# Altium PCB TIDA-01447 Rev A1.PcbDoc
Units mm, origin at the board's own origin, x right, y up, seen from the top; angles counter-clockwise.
Board outline 16 x 21 mm, 2 copper layers (Top Layer, Bottom Layer), stack 1.575 mm thick; 26 components, 8 nets, 40 pads, 0 vias.
Unrouted connection lines stored in the file: 1.
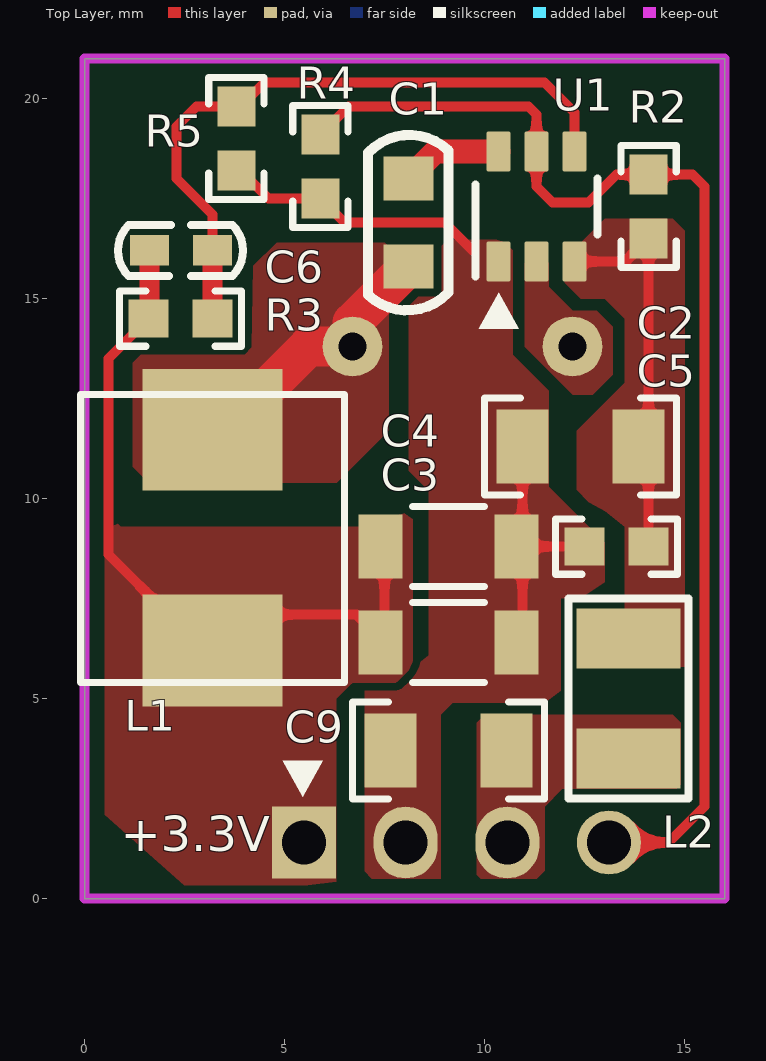
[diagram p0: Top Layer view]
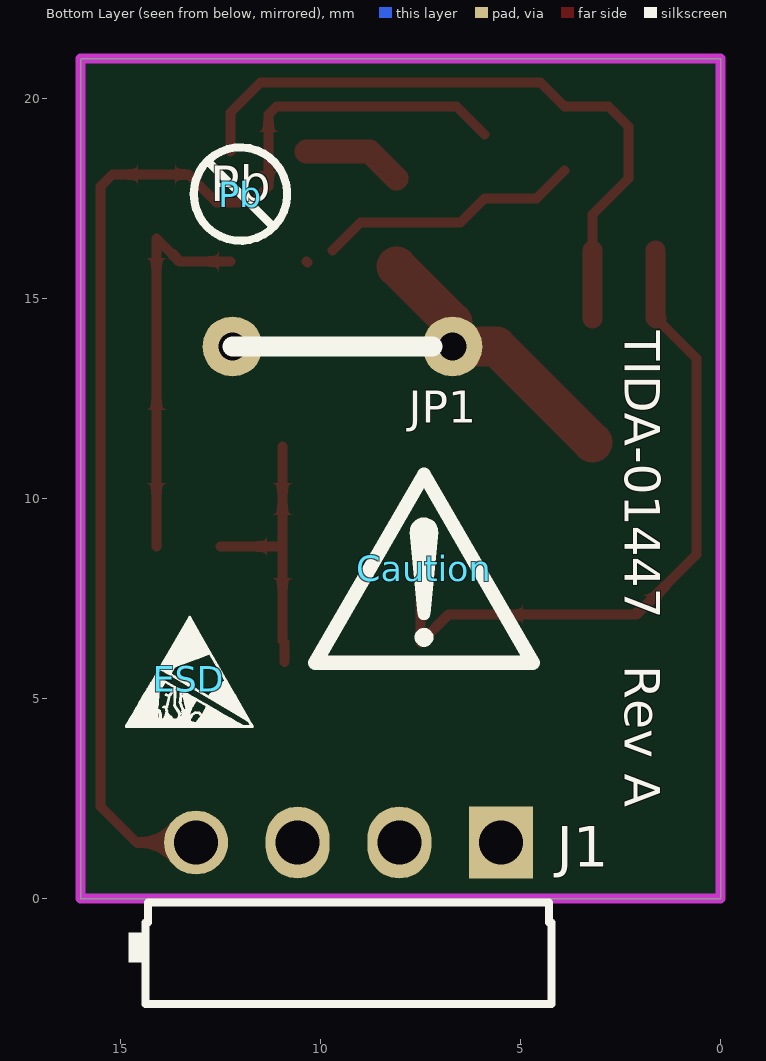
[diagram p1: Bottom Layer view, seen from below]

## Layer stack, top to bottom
Top Solder: solder mask 0.0102, Solder Resist, Dk 3.5
Top Layer: signal copper 0.0356
Dielectric1: core 1.5037, FR-4, Dk 4.8
Bottom Layer: signal copper 0.0356
Bottom Solder: solder mask 0.0102, Solder Resist, Dk 3.5

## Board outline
0,0 0,21 16,21 16,0

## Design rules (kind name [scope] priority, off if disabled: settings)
AcuteAngle [All] p1: minimum=4.50000000000000E+0001 checktracksonly=FALSE
AssemblyTestPointUsage [All] p1: valid=2
Clearance Clearance_Keepouts [((IsTrack Or IsArc) And Not InPoly) And IsFree and IsKeepOut vs ((IsTrack Or IsArc) And Not InPoly) And IsFree and IsKeepOut] p1 off: gap=0
Clearance Clearance_BoardEdge_MountingHoles [OnCopper and InComponentClass('Mounting Holes') vs IsKeepOut] p2 off: gap=1.016
Clearance Clearance_BoardEdge_Poly [OnCopper and InPoly vs IsKeepOut] p3 off: gap=0.635
Clearance Clearance_BoardEdge [OnCopper and Not InComponentClass('Logo') and not InComponentClass('FiducialMark') and not InRegion(1000,500,4000,800) and Not IsKeepout vs IsKeepOut] p4 off: gap=1.905
Clearance Clearance_Poly [InPolygon] p5 off: gap=0.635
Clearance [All] p6: gap=0.2
ComponentClearance ComponentClearance_MountingHoles_FiducialMarks [InComponentClass('Mounting Holes') vs InComponentClass('FiducialMark')] p1: gap=1.27 collisioncheckmode=3 verticalgap=0.254 showdistances=FALSE
ComponentClearance ComponentClearance_Shunt [InComponentClass('Header') vs InComponentClass('Shunt')] p2: gap=0 collisioncheckmode=3 verticalgap=0 showdistances=FALSE
ComponentClearance ComponentClearance_Logo [InComponentClass('Logo')] p3: gap=1.27 collisioncheckmode=3 verticalgap=0.254 showdistances=FALSE
ComponentClearance ComponentClearance_ScrewToNut [(HasFootprint('NY PMS 440 0025 PH')) vs (HasFootprint('Keystone_1902C'))] p4: gap=0.127 collisioncheckmode=3 verticalgap=0.254 showdistances=FALSE
ComponentClearance ComponentClearance_MountingHoles [InComponentClass('Mounting Holes')] p5: gap=6.35 collisioncheckmode=3 verticalgap=2540 showdistances=FALSE
ComponentClearance ComponentClearance_SmallPassives [HasFootprint('0201*') or HasFootprint('0402*') or HasFootprint('0508') or HasFootprint('0603*') or HasFootprint('0612') or HasFootprint('0805*') or HasFootprint('0815*') or HasFootprint('0830*') or HasFootprint('1206*') or HasFootprint('1210*') or HasFootprint('1808*') or HasFootprint('1812*') or HasFootprint('1825*') or HasFootprint('2010*') or HasFootprint('2220*') or HasFootprint('2225*') or HasFootprint('2512*') or HasFootprint('2728*') or HasFootprint('3518*') vs HasFootprint('0201*') or HasFootprint('0402*') or HasFootprint('0508') or HasFootprint('0603*') or HasFootprint('0612') or HasFootprint('0805*') or HasFootprint('0815*') or HasFootprint('0830*') or HasFootprint('1206*') or HasFootprint('1210*') or HasFootprint('1808*') or HasFootprint('1812*') or HasFootprint('1825*') or HasFootprint('2010*') or HasFootprint('2220*') or HasFootprint('2225*') or HasFootprint('2512*') or HasFootprint('2728*') or HasFootprint('3518*')] p6: gap=0.508 collisioncheckmode=3 verticalgap=0.254 showdistances=FALSE
ComponentClearance ComponentClearance_THtoSMT [IsThruComponent vs IsSMTComponent] p7: gap=2.54 collisioncheckmode=3 verticalgap=0.762 showdistances=FALSE
ComponentClearance ComponentClearance_THtoTH [IsThruComponent vs IsThruComponent] p8: gap=3 collisioncheckmode=3 verticalgap=0.762 showdistances=FALSE
ComponentClearance [All] p9: gap=1.016 collisioncheckmode=3 verticalgap=0.254 showdistances=FALSE
DiffPairsRouting [All] p1: maxlimit=2.54 minlimit=0.254 mostfreqgap=0.254 toplayer_minwidth=0.381 toplayer_maxwidth=0.381 toplayer_prefwidth=0.381 bottomlayer_minwidth=0.381 bottomlayer_maxwidth=0.381 bottomlayer_prefwidth=0.381 maxuncoupledlength=25.4
FabricationTestPointUsage TestPointUsage [All] p1: valid=2 allowmultiple=FALSE
FabricationTestpoint Testpoint [All] p1: side=3 testpointundercomponent=TRUE minsize=1.016 maxsize=2.54 preferedsize=1.524 minholesize=0 maxholesize=1.016 preferedholesize=0.813 testpointgrid=0.025 allowsidetop=TRUE allowsidebottom=TRUE usegrid=TRUE gridtolerance=0
FanoutControl Fanout_LCC [IsLCC] p1: bgadir=Out bgaviamode=Centered fanoutstyle=Auto fanoutdirection=Alternating viagrid=0.025 // Fanout_LCC (Default Rule)
FanoutControl Fanout_BGA [IsBGA] p2: bgadir=Out bgaviamode=Centered fanoutstyle=Auto fanoutdirection=Alternating viagrid=0.025 // Fanout_BGA (Default Rule)
FanoutControl Fanout_Default [All] p4: bgadir=Out bgaviamode=Centered fanoutstyle=Auto fanoutdirection=Alternating viagrid=0.025 // Fanout_Default (Default Rule)
FanoutControl Fanout_Small [(CompPinCount < 5)] p5: bgadir=Out bgaviamode=Centered fanoutstyle=Auto fanoutdirection=OutThenIn viagrid=0.025 // Fanout_Small (Default Rule)
HoleSize [All] p1: absolutevalues=TRUE maxlimit=6.375 minlimit=0.203 maxpercent=80.000 minpercent=20.000
MinimumAnnularRing MinimumAnnularRing_ThermalPadVias [IsVia and InAnyComponent] p1: minimumring=0.15
MinimumAnnularRing [All] p2: minimumring=0.229
MinimumSolderMaskSliver MinimumSolderMaskSliver_Logo [InComponentClass('Logo') vs InComponentClass('Logo')] p1: minsoldermaskwidth=0.018
MinimumSolderMaskSliver [All] p2: minsoldermaskwidth=0.1
PlaneConnect [All] p1: planeconnectstyle=Relief reliefexpansion=0.254 reliefentries=4 reliefconductorwidth=0.254 reliefairgap=0.254
PolygonConnect [All] p1: connectstyle=Direct reliefconductorwidth=0.254 reliefentries=4 polygonreliefangle="90 Angle" airgapwidth=0.254
RoutingVias ThermalPadVias [IsVia and InAnyComponent] p1: holewidth=0.2 width=0.5 viastyle="Through Hole" minholewidth=0.2 minwidth=0.5 maxholewidth=0.33 maxwidth=0.6
RoutingVias [All] p2: holewidth=0.406 width=0.864 viastyle="Through Hole" minholewidth=0.2 minwidth=0.66 maxholewidth=1.016 maxwidth=1.651
SilkToBoardRegionClearance [Not ((IsComment or IsDesignator) And (Hide <> 'False')) and not InRegion(1000,500,4000,800)] p1:
SilkToSilkClearance SilkToSilkClearance_Pb-FreeLogo [(HasFootprint('Pb-Free_Overlay_Medium') OR HasFootprint('Pb-Free_Overlay_Small')) vs (HasFootprint('Pb-Free_Overlay_Medium') OR HasFootprint('Pb-Free_Overlay_Small'))] p1: silktosilkclearance=0
SilkToSilkClearance [All] p2: silktosilkclearance=0.102
SilkToSolderMaskClearance SilkToComonentPadClearance [IsPad and InAnycomponent] p1: minsilkscreentomaskgap=0.127 clearancetoexposedcopper=TRUE
SilkToSolderMaskClearance "Silk to Solder Mask Opening" [All] p2: minsilkscreentomaskgap=0.102 clearancetoexposedcopper=FALSE
SolderMaskExpansion [All] p1: expansion=0.05
UnpouredPolygon [All] p1: allowunpoured=FALSE
Width [All] p1: maxlimit=2.54 minlimit=0.152 preferedwidth=0.254 checkconnectedcopper=TRUE
14 further rules are at their usual default settings.

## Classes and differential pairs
component class TIDA-01447: C1 C2 C3 C4 C5 C6 C9 J1 JP1 L1 L2 R2 R3 R4 R5 U1

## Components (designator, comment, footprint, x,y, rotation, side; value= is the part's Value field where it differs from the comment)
C1 "GRM21BR71E104KA01L" C/0805/SMT1 8.1,15.9 r90 top
C2 "GRM31CR71E106KA12L" 1206 12.4,11.3 r180 top
C3 "GCM31CR71A226KE02" 1206_190 9.1,6.4 r0 top
C4 "GCM31CR71A226KE02" 1206_190 9.1,8.8 r0 top
C5 "GRM188R71E104KA01D" 0603 13.3,8.8 r180 top
C6 "06033C101KAT2A" C/0603 2.4,16.2 r0 top
C9 "GRM31CR71E106KA12L" 1206 9.1,3.7 r180 top
Caution "CAUTION.  READ USER GUIDE BEFORE USE" IEC_Caution_small 7.412,8.254 r180 bottom
ESD "ESD Susceptible" ESD_Overlay_small 13.3,5.5 r180 bottom
H5 "1902C" Keystone_1902C -38.24,60.15 r180 bottom locked
H6 "1902C" Keystone_1902C 77.33,60.15 r180 bottom locked
H7 "1902C" Keystone_1902C -38.24,-17.32 r180 bottom locked
H8 "1902C" Keystone_1902C 77.33,-17.32 r180 bottom locked
J1 "61300411021" Wurth_61300411021 9.3,1.4 r180 bottom
JP1 "CRCW0603100KFKEA" JUMP-5 7.2,13.8 r0 bottom
L1 "ABG06B45M220" WE-PD-M 3.2,9 r270 top
L2 "ABG03A15M4R7" Inductor-EPL3015 13.6,5 r90 top
Pb "Pb-Free Symbol" Pb-Free_Overlay_Small 12.001,17.611 r180 bottom
R2 "CRCW0603510KJNEA" 0603 14.1,17.3 r270 top
R3 "CRCW0603100KFKEA" 0603 2.4,14.5 r180 top
R4 "CRCW0603118KFKEA" 0603 5.9,18.3 r90 top
R5 "CRCW060313K3FKEA" 0603 3.8,19 r90 top
U1 "TPS54202DDCR" DDC0006A_N 11.3,17.3 r90 top
ZZ2 "These assemblies are ESD sensitive, ESD precautions shall be observed." AssemblyNote -38.621,74.859 r0 top
ZZ3 "These assemblies must be clean and free from flux and all contaminants. Use of no clean flux is not acceptable." AssemblyNote -38.621,72.61 r0 top
ZZ4 "These assemblies must comply with workmanship standards IPC-A-610 Class 2, unless otherwise specified." AssemblyNote -38.621,70.361 r0 top

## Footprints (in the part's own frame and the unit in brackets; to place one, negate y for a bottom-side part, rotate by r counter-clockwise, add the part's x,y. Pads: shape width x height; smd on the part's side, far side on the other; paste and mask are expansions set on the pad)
0603 [mm] "0603 from SM-752 data"
  rect 1x0.95 smd: 1(-0.8,0) 2(0.8,0)
  silkscreen extent -1.52,-0.69 1.52,0.69, body extent -0.87,-0.47 0.87,0.47, height 1
1206 [mm] "1206 from SM-752 data"
  rect 1.3x1.85 smd: 1(-1.45,0) 2(1.45,0)
  silkscreen extent -2.4,-1.21 2.4,1.21, body extent -1.7,-0.9 1.7,0.9, height 1.35
1206_190 [mm] "1206_190"
  rect 1.1x1.6 smd: 1(-1.7,0) 2(1.7,0)
  silkscreen extent -0.9,-1 0.9,1, body extent -1.75,-0.95 1.75,0.95, height 1.9
AssemblyNote [mm] "Assembly Note"
C/0603 [mil]
  rect 38x30 smd: 1(-30.52,0.06) 2(31.48,0.06)
  silkscreen extent -62,-25 62,25
C/0805/SMT1 [mm]
  rect 1.1x1.25 smd: 1(-0.1,0) 2(2.1,0)
  silkscreen extent -1.19,-1 3.19,1.01
DDC0006A_N [mm]
  rrect17% 1x0.6 smd: 1(-1.375,0.95) 2(-1.375,0) 3(-1.375,-0.95) 4(1.375,-0.95) 5(1.375,0) 6(1.375,0.95)
  silkscreen extent -1.75,-1.52 0.7,1.53, body extent -1.43,-1.48 1.43,1.49, height 0.92
ESD_Overlay_small [mm]
  silkscreen extent -1.58,-1.23 1.62,1.55
IEC_Caution_small [mm]
  silkscreen extent -2.72,-2.36 2.72,2.35
Inductor-EPL3015 [mm]
  rect 1.5x2.6 smd: 1(-1.5,0) 2(1.5,0)
  silkscreen extent -2.5,-1.5 2.5,1.5
JUMP-5 [mm]
  round 1.5 hole 0.7: 1(-0.5,0) 2(5,0)
  silkscreen extent 0,0 5,0
Keystone_1902C [mm] "Hex Standoff, 4-40 threaded, nylon"
  body extent -3.68,-3.2 3.71,3.2, height 12.73
Pb-Free_Overlay_Small [mm]
  silkscreen extent -1.17,-1.17 1.16,1.17
WE-PD-M [mm] "Wurth Elektronik recommended land pattern, 2008-01-04"
  rect 2.4x3.5 smd: 1(-3.035,0) 2(3.004,0)
  silkscreen extent -3.6,-3.3 3.6,3.3, body extent -3.81,-3.84 3.81,3.79, height 4.5
Wurth_61300411021 [mm] "Header, 2.54 mm, 4x1, R/A, TH"
  round 1.6 hole 1.1: 1(-3.81,0)
  oval 1.6x1.8 hole 1.1: 2(-1.27,0) 3(1.27,0)
  rect 1.6x1.8 hole 1.1: 4(3.81,0)
  silkscreen extent -5.5,-4.04 5.08,-1.5, body extent -5.08,-10.04 5.08,0.32, height 2.55

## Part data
C1: "CAP, CERM, 0.1 μF, 25 V, +/- 10%, X7R, 0805"
C2 C9: "CAP, CERM, 10 μF, 25 V, +/- 10%, X7R, 1206"
C3 C4: "CAP, CERM, 22 μF, 10 V, +/- 10%, X7R, AEC-Q200 Grade 1, 1206_190"
C5: "CAP, CERM, 0.1 μF, 25 V, +/- 10%, X7R, 0603"
C6: "CAP, CERM, 100 pF, 25 V, +/- 10%, X7R, 0603"
Caution: library part IEC_Caution, "IEC 61010-1 Caution Warning"
ESD: library part ESD_Susceptible, "ESD Susceptible Symbol"
H5 H6 H7 H8: "Standoff, Hex, 0.5\"L #4-40 Nylon"
J1: "Header, 2.54 mm, 4x1, Gold, R/A, TH"
JP1 R3: "RES, 100 k, 1%, 0.1 W, 0603"
L1 L2: library part LPS8045B-333MRB, "Inductor, Shielded, Ferrite, 22 μH, 3.3 A, SMD"
Pb: library part Pb-Free
R2: "RES, 510 k, 5%, 0.1 W, 0603"
R4: "RES, 118 k, 1%, 0.1 W, 0603"
R5: "RES, 13.3 k, 1%, 0.1 W, 0603"
U1: "4.5-V TO 28-V INPUT, 2-A OUTPUT, EMI FRIENDLY SYNCHRONUOUS STEP-DOWN CONVERTOR, DDC0006A"
ZZ2 ZZ3 ZZ4: library part AssemblyNote

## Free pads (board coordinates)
  rect 3.5x2 smd: 0(3.2,6.6)
  rect 3.5x2.4 smd: 0(3.2,11.4)

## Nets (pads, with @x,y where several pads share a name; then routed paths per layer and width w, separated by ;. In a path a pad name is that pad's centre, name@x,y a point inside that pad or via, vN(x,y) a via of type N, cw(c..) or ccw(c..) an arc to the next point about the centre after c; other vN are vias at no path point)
+5V: C3.1 C4.1 C6.1 J1.4 L1.2 pad.0@3.2,6.6 R3.2 | length 18
  Top Layer w0.254: R3.2 0.6,13.5 0.6,8.6 2.104,7.097 6.804,7.097 7.5,6.4 C4.1@7.5,8.6
  Top Layer w0.5: R3.2 1.625,14.525 C6.1
EN: J1.1 R2.1 R4.2 U1.5 | length 30.6
  Top Layer w0.254: R4.2 6.6,19.8 11.1,19.8 11.3,19.6 U1.5 11.3,17.8 11.7,17.4 12.6,17.4 13.3,18.1 R2.1 15.2,18.1 15.5,17.8 15.5,2.3 14.6,1.4 J1.1
GND: C2.2 C3.2 C4.2 C5.2 C9.2 J1.3 R4.1 R5.1 U1.1 | length 13.6
  Top Layer w0.254: R5.1@3.9,18.2 4.6,17.5 R4.1 6.5,16.9 9,16.9 9.7,16.2 ; U1.1@10.325,15.9 U1.1 ; C3.2@10.9,5.912 C3.2@10.9,6.4 ; C3.2@10.95,6.45 C4.2@10.95,8.8 ; C2.2 C4.2@10.95,8.8 ; C5.2 C4.2@10.95,8.8
NetC1_1: C1.1 JP1.1 JP1.2 L1.1 pad.0@3.2,11.4 U1.2 | length 7.1
  Top Layer w1: L1.1@3.2,11.4 5.6,13.8 JP1.1 6.7,14.4 C1.1
NetC1_2: C1.2 U1.6 | length 2.5
  Top Layer w0.6: C1.2 8.775,18.675 U1.6
NetC2_1: C2.1 C5.1 L2.2 R2.2 U1.3 | length 9.8
  Top Layer w0.254: U1.3 13.525,15.925 R2.2 C5.1
NetC6_2: C6.2 R3.1 R5.2 U1.4 | length 16.9
  Top Layer w0.254: C6.2 3.2,17.1 2.3,18 2.3,19.3 2.8,19.8 R5.2 3.9,19.8 4.5,20.4 11.5,20.4 12.25,19.65 U1.4
  Top Layer w0.5: R3.1 C6.2
VIN: C9.1 J1.2 L2.1

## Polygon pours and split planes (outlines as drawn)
VIN on Top Layer "Top Layer-No Net 5" (solid, remove dead copper, pour order 7): 10.7,4.6 14.7,4.6 14.9,4.4 14.9,3 14.9,2.851 14.795,2.746 11.946,2.746 11.5,2.3 11.5,0.7 11.3,0.5 9.9,0.5 9.8,0.6 9.8,4.4 10,4.6
GND on Top Layer "Top Layer-No Net" (solid, remove dead copper, pour order 2): 10.535,16.397 10.7,16.232 10.7,13.8 10.7,13.6 11.2,13.1 11.6,12.7 11.6,11.8 11.6,10.3 12.1,9.8 13,8.9 13,7.908 12.523,7.577 11.9,7.5 11.9,6.087 11.9,5.2 11.5,4.9 9.2,4.9 8.9,4.6 8.9,0.5 7,0.5 7,5.6 8.033,5.6 8.6,6.087 8.6,10.2 8.3,10.5 8.1,10.7 8.1,14.2 8.1,15.5 9.072,16.472 10.535,16.472
NetC2_1 on Top Layer "Top Layer-No Net 1" (solid, remove dead copper, pour order 4): 12,16.1 12,15.4 12.3,15.1 12.4,15 12.9,15 13,15 13.4,14.6 13.5,14.5 13.5,13.4 13.5,12.9 13.2,12.6 12.3,11.7 12.3,11 12.3,10.223 12.611,9.912 13.015,9.679 13.5,9.3 13.5,8.8 13.5,5.8 15,5.8 15,9.3 15,16.7 14.8,16.9 14.7,17 13.6,17 13,17 12.4,16.4
NetC1_1 on Top Layer "Top Layer-No Net 2" (solid, remove dead copper, pour order 6): 7.6,14.008 7.6,11.7 7,11.1 6.3,10.4 2.5,10.4 1.6,10.4 1.2,10.8 1.2,13.4 1.4,13.6 3.8,13.6 4,13.6 4.181,13.781 4.219,15.819 4.8,16.4 7.5,16.4 7.6,16.3
NetC1_1 on Top Layer "Top Layer-No Net 3" (solid, remove dead copper, pour order 8): 11.6,15.9 11.6,15.3 11.8,15.1 12.2,14.7 12.6,14.7 12.8,14.7 13,14.5 13.2,14.3 13.2,13.7 13.2,13.1 12.9,12.8 12.7,12.6 12.3,12.6 12.2,12.6 11.7,13.1 11,13.8 11,15 11,15.9
+5V on Top Layer "Top Layer-No Net 4" (solid, remove dead copper, pour order 10): 8.2,9.7 8.2,5.8 7.8,5.4 6.7,5.4 6.632,5.332 6.3,5 6.3,0.42 2.857,0.008 0.5,2.1 0.5,8.8 0.6,8.9 0.6,9.6 0.9,9.3 6.9,9.3

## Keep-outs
Keep-Out Layer:
  lines w0.254: -43.447,-22.4 ccw(c-43.32,-22.4) -43.32,-22.527 cw(c-43.32,-22.4) -43.447,-22.4 ; 0,0 0,21 16,21 16,0 0,0

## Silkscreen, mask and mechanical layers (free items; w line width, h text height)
Top Overlay:
  region: 10.35,15.15 9.85,14.25 10.85,14.25
  region: 5.45,2.55 5.95,3.45 4.95,3.45
  text "+3.3V" at 0.9,0.9 h1.5
Bottom Overlay:
  text "TIDA-01447   Rev A" at 2.7,14.2 h1.52 r90
Top Paste:
  text ".Layer_Name" at -28.664,-44.206 h1.52
Bottom Paste:
  text ".Layer_Name" at -28.664,-44.206 h1.52
Top Solder:
  lines w1: 8.6,13.1 8.6,14.5 ; 9.1,10.6 9.1,12 ; 10.1,13.2 10.1,14.8 ; 14.2,13.3 14.2,15
Bottom Solder:
  text ".Layer_Name" at -28.664,-44.206 h1.52
Drill Guide:
  text ".Layer_Name" at -28.664,-44.206 h1.52
M1 Board Outline:
  lines w0.254: -43.32,-22.4 82.41,-22.4 82.41,65.23 -43.32,65.23 -43.32,-22.4
  text ".Layer_Name" at -28.664,-44.206 h1.52
M2 Board Dimensions:
  rectangle: -40.145,-32.56 -30.62,-29.385
  rectangle: -43.32,-29.385 -40.145,-26.21
  lines w0.178: -43.32,-29.385 -17.92,-29.385 ; -40.145,-32.56 -40.145,-26.21 ; -36.97,-32.56 -36.97,-26.21 ; -30.62,-32.56 -30.62,-26.21 ; -24.27,-32.56 -24.27,-26.21 ; -43.32,-32.56 -43.32,-26.21 -17.92,-26.21 -17.92,-32.56 -43.32,-32.56
  text ".Layer_Name" at -28.664,-44.206 h1.52
M3 3D STEP Top:
  text ".Layer_Name" at -28.664,-44.206 h1.52
M4 3D STEP Bottom:
  text ".Layer_Name" at -28.664,-44.206 h1.52
M5 Assembly Top:
  lines w0.254: -50.737,-46.026 116.903,-46.026 ; -50.737,-40.862 116.954,-40.862 ; -50.737,-35.697 -50.737,-51.191 50.99,-51.191 116.954,-51.191 116.954,-35.697 -50.724,-35.697 -50.724,-51.191 -10.706,-51.191 ; 11.874,-51.191 11.874,-35.697 ; 44.056,-40.862 44.056,-35.697 ; 65.392,-40.862 65.392,-35.697 ; 81.191,-51.356 81.191,-46.204
  text "COMPONENTS MARKED 'DNP' SHOULD NOT BE POPULATED." at -14.021,-30.49 h1.52
  text "ASSEMBLY VARIANT:" at -14.034,-33.424 h1.52
  text ".VariantName" at 12.281,-33.424 h1.52
  text "PCB VIEWED FROM TOP SIDE" at -49.124,-39.054 h1.52
  text "BOARD #:" at 13.779,-39.054 h1.52
  text ".PRJ_Number" at 27.635,-39.054 h1.52
  text "REV:" at 49.085,-39.054 h1.52
  text ".PCB_Rev" at 56.489,-39.054 h1.52
  text "SVN REV:" at 70.37,-39.054 h1.52
  text ".VersionControl_RevNumber" at 83.223,-39.054 h1.52
  text "TID #:" at 13.779,-44.219 h1.52
  text ".TID" at 27.635,-44.219 h1.52
  text "PLOT NAME =" at -49.124,-49.434 h1.52
  text ".plot_File_Name" at -28.664,-49.434 h1.52
  text "GENERATED    :" at 13.83,-49.434 h1.52
  text ".Print_Date" at 35.915,-49.434 h1.52
  text ".Print_Time" at 54.432,-49.434 h1.52
  text "TEXAS INSTRUMENTS" at 86.55,-49.434 h1.52
M6 Assembly Bottom:
  lines w0.254: -50.749,-40.874 116.941,-40.874 ; -50.699,-46.039 116.941,-46.039 ; -14.986,-51.369 -14.986,-46.217 ; 0.813,-40.874 0.813,-35.71 ; 22.149,-40.874 22.149,-35.71 ; 54.33,-51.204 54.33,-35.71 ; 76.911,-51.204 116.929,-51.204 116.929,-35.71 -50.749,-35.71 -50.749,-51.204 15.214,-51.204 116.941,-51.204 116.941,-35.71
  text "COMPONENTS MARKED 'DNP' SHOULD NOT BE POPULATED." at 111.671,-30.477 h1.52
  text ".VariantName" at 85.153,-33.424 h1.52
  text "ASSEMBLY VARIANT:" at 111.544,-33.424 h1.52
  text ".VersionControl_RevNumber" at -17.018,-39.067 h1.52
  text "SVN REV:" at -4.166,-39.067 h1.52
  text ".PCB_Rev" at 9.715,-39.067 h1.52
  text "REV:" at 17.119,-39.067 h1.52
  text ".PRJ_Number" at 38.57,-39.067 h1.52
  text "BOARD #:" at 52.425,-39.067 h1.52
  text "PCB VIEWED FROM BOTTOM SIDE" at 115.328,-39.067 h1.52
  text ".TID" at 38.57,-44.231 h1.52
  text "TID #:" at 52.425,-44.231 h1.52
  text "TEXAS INSTRUMENTS" at -20.346,-49.447 h1.52
  text ".Print_Time" at 11.773,-49.447 h1.52
  text ".Print_Date" at 30.289,-49.447 h1.52
  text "GENERATED    :" at 52.375,-49.447 h1.52
  text ".plot_File_Name" at 94.869,-49.447 h1.52
  text "PLOT NAME =" at 115.328,-49.447 h1.52
M9 Title Sheet:
  drawing of 57 lines, arcs and shapes, not listed
  text "1" at -24.528,181.727 h1.78
  text "2" at 38.862,181.727 h1.78
  text "3" at 102.091,181.727 h1.78
  text "4" at 165.76,181.727 h1.78
  text "5" at 229.235,181.727 h1.78
  text "6" at 292.862,181.727 h1.78
  text "A" at -53.899,152.695 h1.78
  text "A" at 322.021,152.695 h1.78
  text "B" at -53.899,92.243 h1.78
  text "B" at 322.021,92.243 h1.78
  text "C" at -53.899,31.918 h1.78
  text "C" at 322.021,31.918 h1.78
  text "PROJECT TITLE:" at 244.805,-15.351 h1.14
  text "TIDA-00948" at 246.075,-18.738 h1.78
  text "DESIGNED FOR:" at 244.805,-22.997 h1.14
  text "D" at -53.899,-28.28 h1.78
  text "D" at 322.021,-28.28 h1.78
  text "FILE NAME:" at 244.805,-30.617 h1.14
  text ".PCB_File_Name_No_Path" at 246.075,-33.665 h1.78
  text "Texas Instruments (TI) and/or its licensors do not warrant the accuracy or completeness of this specification" at 118.58,-37.776 h1.14
  text "ENGINEER:" at 244.805,-37.983 h1.14
  text "LAYOUT BY:" at 283.032,-37.983 h1.14
  text "or any information contained therein. TI and/or its licensors do not warrant that this design will meet" at 117.437,-40.637 h1.14
  text "Jason Tao" at 246.075,-41.92 h1.78
  text "Jason Tao" at 284.315,-41.92 h1.78
  text "the specifications, will be suitable for your application or fit for any particular purpose, or will operate in" at 117.437,-43.499 h1.14
  text ".Layer_Name" at -28.664,-44.206 h1.52
  text "ALTIUM DESIGNER VERSION:" at 283.032,-45.857 h1.14
  text "an implementation. TI and/or its licensors do not warrant that the design is production worthy. You should" at 117.437,-46.361 h1.14
  text "completely validate and test your design implementation to confirm the system functionality for your application." at 118.58,-49.222 h1.14
  text ".print_Scale" at 246.075,-49.243 h1.78
  text ".Application_BuildNumber" at 284.315,-49.243 h1.78
  text "1" at -24.528,-54.493 h1.78
  text "2" at 38.862,-54.493 h1.78
  text "3" at 102.091,-54.493 h1.78
  text "4" at 165.76,-54.493 h1.78
  text "5" at 229.235,-54.493 h1.78
  text "6" at 292.862,-54.493 h1.78
M10 Fab Notes:
  drawing of 173 lines, arcs and shapes, not listed
  text "DESIGN INFORMATION" at 271.056,135.105 h1.52
  text "MIN. TRACK WIDTH:" at 254.684,130.533 h1.52
  text "8" at 282.529,130.533 h1.52
  text "MIL" at 286.46,130.533 h1.52
  text "MIN. CLEARANCE:" at 254.684,127.181 h1.52
  text "0.2" at 281.005,127.181 h1.52
  text "mm" at 286.46,127.181 h1.52
  text "MIN. VIA PAD SIZE:" at 254.684,123.828 h1.52
  text "24" at 281.767,123.828 h1.52
  text "MIL" at 286.46,123.828 h1.52
  text "0.05mm (2MIL)" at 272.337,120.228 h1.52
  text "MINIMUM ANNULAR RING" at 246.322,120.12 h1.52
  text "EXTERNAL" at 290.321,120.12 h1.52
  text "PER" at 251.402,117.122 h1.52
  text "IPC-D-275 CLASS 2 LEVEL C" at 256.99,117.122 h1.52
  text "MIL, HOLES" at 294.791,114.27 h1.52
  text "+/-" at 284.823,114.252 h1.52
  text "+/-" at 306.514,114.252 h1.52
  text "REGISTRATION TOLERANCES:" at 246.322,114.125 h1.52
  text "METAL" at 276.796,114.125 h1.52
  text "5" at 291.432,114.125 h1.52
  text "3" at 312.59,114.125 h1.52
  text "MIL" at 315.543,114.125 h1.52
  text "+/-" at 306.514,111.255 h1.52
  text "HOLE SIZE TOLERANCE (UNLESS OTHERWISE SPECIFIED):" at 246.322,111.128 h1.52
  text "3" at 312.59,111.128 h1.52
  text "MIL" at 315.543,111.128 h1.52
  text "MATERIAL:" at 244.423,105.808 h1.52
  text "FR-4 High Tg" at 269.479,102.243 h1.52
  text "FR-408" at 255.116,102.025 h1.52
  text "OTHER" at 292.911,102.025 h1.52
  text "X" at 265.544,101.933 h1.52
  text "62 MIL (1.6mm) +/-10%" at 263.247,97.892 h1.52
  text "THICKNESS:" at 246.322,97.784 h1.52
  text "X" at 259.991,97.784 h1.52
  text "OTHER" at 295.883,97.784 h1.52
  text "TOLERANCE:" at 246.322,93.77 h1.52
  text "X" at 267.64,93.77 h1.52
  text "ANSI IPC-6012 TYPE 3 CLASS 2" at 272.389,93.77 h1.52
  text "OTHER +/-" at 272.388,89.808 h1.52
  text "BOW & TWIST:" at 246.322,85.82 h1.52
  text "X" at 267.64,85.82 h1.52
  text "ANSI IPC-6012 TYPE 3 CLASS 2" at 272.389,85.82 h1.52
  text "OTHER +/-" at 272.388,81.794 h1.52
  text "DRILLING:" at 244.423,78.276 h1.52
  text "REFERENCE:" at 246.322,75.305 h1.52
  text "X" at 262.787,75.305 h1.52
  text "AS SHOWN" at 267.537,75.305 h1.52
  text "X" at 285.672,75.305 h1.52
  text "NC_DRILL FILES" at 289.152,75.305 h1.52
  text "PTH MIN COPPER THICKNESS:" at 246.322,71.291 h1.52
  text "X" at 280.618,71.291 h1.52
  text "1MIL" at 284.098,71.291 h1.52
  text "OTHER" at 296.721,71.291 h1.52
  text "BOARD FINISH:" at 244.423,67.253 h1.52
  text "SILKSCREEN:" at 248.366,64.256 h1.52
  text "X" at 272.464,64.256 h1.52
  text "TOP" at 275.665,64.256 h1.52
  text "X" at 285.418,64.256 h1.52
  text "BOTTOM" at 288.644,64.256 h1.52
  text "SILKSCREEN COLOR:" at 248.366,60.014 h1.52
  text "X" at 272.438,60.014 h1.52
  text "WHITE" at 275.665,60.014 h1.52
  text "OTHER" at 288.644,60.014 h1.52
  text "X" at 275.766,55.97 h1.52
  text "GREEN" at 278.992,55.97 h1.52
  text "OTHER" at 294.689,55.97 h1.52
  text "SOLDER RESIST COLOR:" at 248.366,55.696 h1.52
  text "X" at 275.766,51.652 h1.52
  text "MATTE" at 278.992,51.652 h1.52
  text "SEMI-GLOSS" at 294.678,51.636 h1.52
  text "IMMERSION GOLD (ENIG)" at 271.372,46.864 h1.52
  text "ENEPIG" at 305.346,46.78 h1.52
  text "SURFACE FINISH:" at 244.423,46.755 h1.52
  text "X" at 266.624,46.755 h1.52
  text "IMM. TIN/SILVER OR EQUIV" at 252.793,42.767 h1.52
  text "OTHER" at 289.152,42.767 h1.52
  text "ARRAY/PANEL:" at 244.423,38.221 h1.52
  text "CUT AND TRIM PER M1 BOARD OUTLINE" at 271.372,38.112 h1.52
  text "N.C. ROUTE" at 271.372,34.258 h1.52
  text "X" at 288.619,34.258 h1.52
  text "V. SCORE" at 293.369,34.258 h1.52
  text "CERTIFICATION:" at 244.423,30.778 h1.52
  text "MATERIALS AND WORKMANSHIP FOR ALL PCBS" at 262.838,30.778 h1.52
  text "TO MEET OR EXCEED THE REQUIREMENTS OF:" at 262.838,28.289 h1.52
  text "X" at 253.351,24.822 h1.52
  text "ANSI IPC-A-600F CLASS ->" at 256.882,24.822 h1.52
  text "X" at 298.514,24.822 h1.52
  text "2" at 301.535,24.822 h1.52
  text "1" at 293.534,24.784 h1.52
  text "3" at 310.526,24.784 h1.52
  text "X" at 274.028,20.771 h1.52
  text "RoHS" at 277.506,20.771 h1.52
  text "OTHER" at 293.874,20.771 h1.52
  text "PER ORDER" at 303.96,20.771 h1.52
  text "ALL BOARDS MUST MEET OR EXCEED UL94-V0 REQUIREMENTS." at 245.122,16.564 h1.52
  text "PCB MUST BEAR THE UL94V-0 UL REGISTERED MATERIAL ID NUMBER" at 245.122,13.516 h1.52
  text "ADDITIONAL REQUIREMENTS:" at 244.423,9.112 h1.52
  text "MICROSECTION:" at 246.322,6.191 h1.52
  text "YES" at 269.328,6.191 h1.52
  text "REQUIRED" at 291.21,2.225 h1.52
  text "BARE BOARD ELEC. TEST:" at 246.322,2.153 h1.52
  text "NONE" at 279.488,2.153 h1.52
  text "X" at 287.984,2.153 h1.52
  text "PER ORDER" at 306.246,2.153 h1.52
  text ".Layer_Name" at -28.664,-44.206 h1.52
M11 Gerber Information:
  lines w0.254: -50.737,-46.026 116.903,-46.026 ; -50.737,-40.862 116.954,-40.862 ; -50.737,-35.697 -50.737,-51.191 50.99,-51.191 116.954,-51.191 116.954,-35.697 -50.724,-35.697 -50.724,-51.191 -10.706,-51.191 ; 11.874,-51.191 11.874,-35.697 ; 44.056,-40.862 44.056,-35.697 ; 65.392,-40.862 65.392,-35.697 ; 81.191,-51.356 81.191,-46.204
  text "ALL ARTWORK VIEWED FROM TOP SIDE" at -49.124,-39.054 h1.52
  text "BOARD #:" at 13.779,-39.054 h1.52
  text ".PRJ_Number" at 27.635,-39.054 h1.52
  text "REV:" at 49.085,-39.054 h1.52
  text ".PCB_Rev" at 56.489,-39.054 h1.52
  text "SVN REV:" at 70.37,-39.054 h1.52
  text ".VersionControl_RevNumber" at 83.223,-39.054 h1.52
  text "LAYER NAME =" at -49.124,-44.206 h1.52
  text "TID #:" at 13.779,-44.219 h1.52
  text ".TID" at 27.635,-44.219 h1.52
  text "PLOT NAME =" at -49.124,-49.434 h1.52
  text ".plot_File_Name" at -28.664,-49.434 h1.52
  text "GENERATED    :" at 13.83,-49.434 h1.52
  text ".Print_Date" at 35.915,-49.434 h1.52
  text ".Print_Time" at 54.432,-49.434 h1.52
  text "TEXAS INSTRUMENTS" at 86.55,-49.434 h1.52
M12 Stackup:
  drawing of 191 lines, arcs and shapes, not listed
  text "Layer" at 205.361,176.482 h1.52
  text "Name" at 215.772,176.482 h1.52
  text "Material" at 239.388,176.482 h1.52
  text "Thickness" at 261.226,176.482 h1.52
  text "Constant" at 277.732,176.482 h1.52
  text "Board Layer Stack" at 292.206,176.482 h1.52
  text "1" at 205.361,173.434 h1.52
  text "Top Overlay" at 215.772,173.434 h1.52
  text "2" at 205.361,170.386 h1.52
  text "Top Solder" at 215.772,170.386 h1.52
  text "Solder Resist" at 239.388,170.386 h1.52
  text "0.40mil" at 261.226,170.386 h1.52
  text "3.5" at 277.732,170.386 h1.52
  text "3" at 205.361,167.338 h1.52
  text "Top Layer" at 215.772,167.338 h1.52
  text "Copper" at 239.388,167.338 h1.52
  text "1.40mil" at 261.226,167.338 h1.52
  text "4" at 205.361,164.29 h1.52
  text "Dielectric1" at 215.772,164.29 h1.52
  text "FR-4" at 239.388,164.29 h1.52
  text "59.20mil" at 261.226,164.29 h1.52
  text "4.8" at 277.732,164.29 h1.52
  text "5" at 205.361,161.242 h1.52
  text "Bottom Layer" at 215.772,161.242 h1.52
  text "Copper" at 239.388,161.242 h1.52
  text "1.40mil" at 261.226,161.242 h1.52
  text "6" at 205.361,158.194 h1.52
  text "Bottom Solder" at 215.772,158.194 h1.52
  text "Solder Resist" at 239.388,158.194 h1.52
  text "0.40mil" at 261.226,158.194 h1.52
  text "3.5" at 277.732,158.194 h1.52
  text "7" at 205.361,155.146 h1.52
  text "Bottom Overlay" at 215.772,155.146 h1.52
  text ".Layer_Name" at -28.664,-44.206 h1.52
M13 Component Bodies Top:
  text ".Layer_Name" at -28.664,-44.206 h1.52
M14 Component Bodies Bottom:
  text ".Layer_Name" at -28.664,-44.206 h1.52
M15 Courtyards Top:
  text ".Layer_Name" at -28.664,-44.206 h1.52
M16 Courtyards Bottom:
  text ".Layer_Name" at -28.664,-44.206 h1.52
Drill Drawing:
  circle w0.025: c98.227,55.622 r0.632
  lines w0.025: 97.595,60.047 98.859,60.047 98.227,58.782 97.595,60.047
  lines w0.305: 95.872,53.852 149.67,53.852 ; 95.872,61.437 149.67,61.437 ; 105.279,50.059 105.279,65.23 ; 114.347,50.059 114.347,65.23 ; 131.151,50.059 131.151,65.23 ; 138.368,50.059 138.368,65.23 ; 95.872,50.059 149.67,50.059 149.67,65.23 95.872,65.23 95.872,50.059
  text "Symbol" at 98.148,62.575 h1.83
  text "Quantity" at 106.417,62.575 h1.83
  text "Finished Hole Size" at 115.485,62.575 h1.83
  text "Plated" at 132.289,62.575 h1.83
  text "Hole Type" at 139.506,62.575 h1.83
  text "2" at 106.417,58.782 h1.52
  text "27.56mil (0.700mm)" at 115.485,58.782 h1.52
  text "PTH" at 132.289,58.782 h1.52
  text "Round" at 139.506,58.782 h1.52
  text "4" at 106.417,54.99 h1.52
  text "43.31mil (1.100mm)" at 115.485,54.99 h1.52
  text "PTH" at 132.289,54.99 h1.52
  text "Round" at 139.506,54.99 h1.52
  text "6 Total" at 106.417,51.197 h1.52
  text ".Layer_Name" at -28.664,-44.206 h1.52

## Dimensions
-43.32,-22.4 to 0,21 on M2 Board Dimensions
-43.32,-22.4 to 16,0 on M2 Board Dimensions
-43.32,-32.56 to -17.92,-32.56 on M2 Board Dimensions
